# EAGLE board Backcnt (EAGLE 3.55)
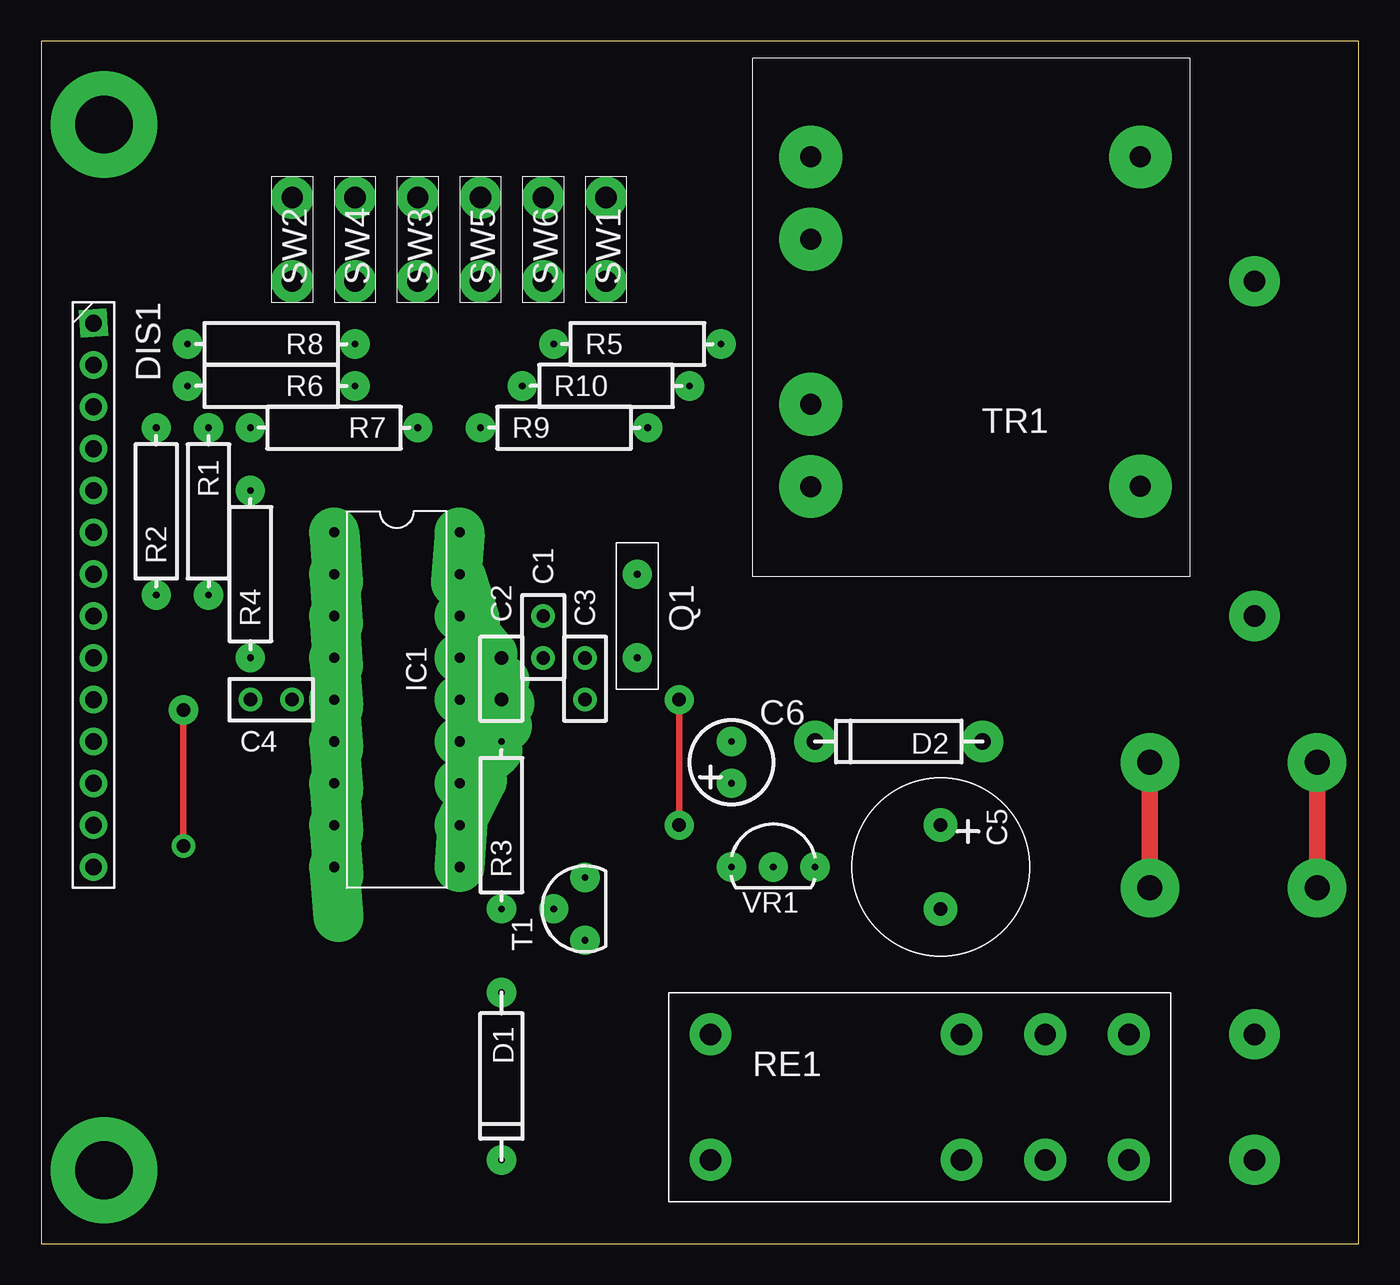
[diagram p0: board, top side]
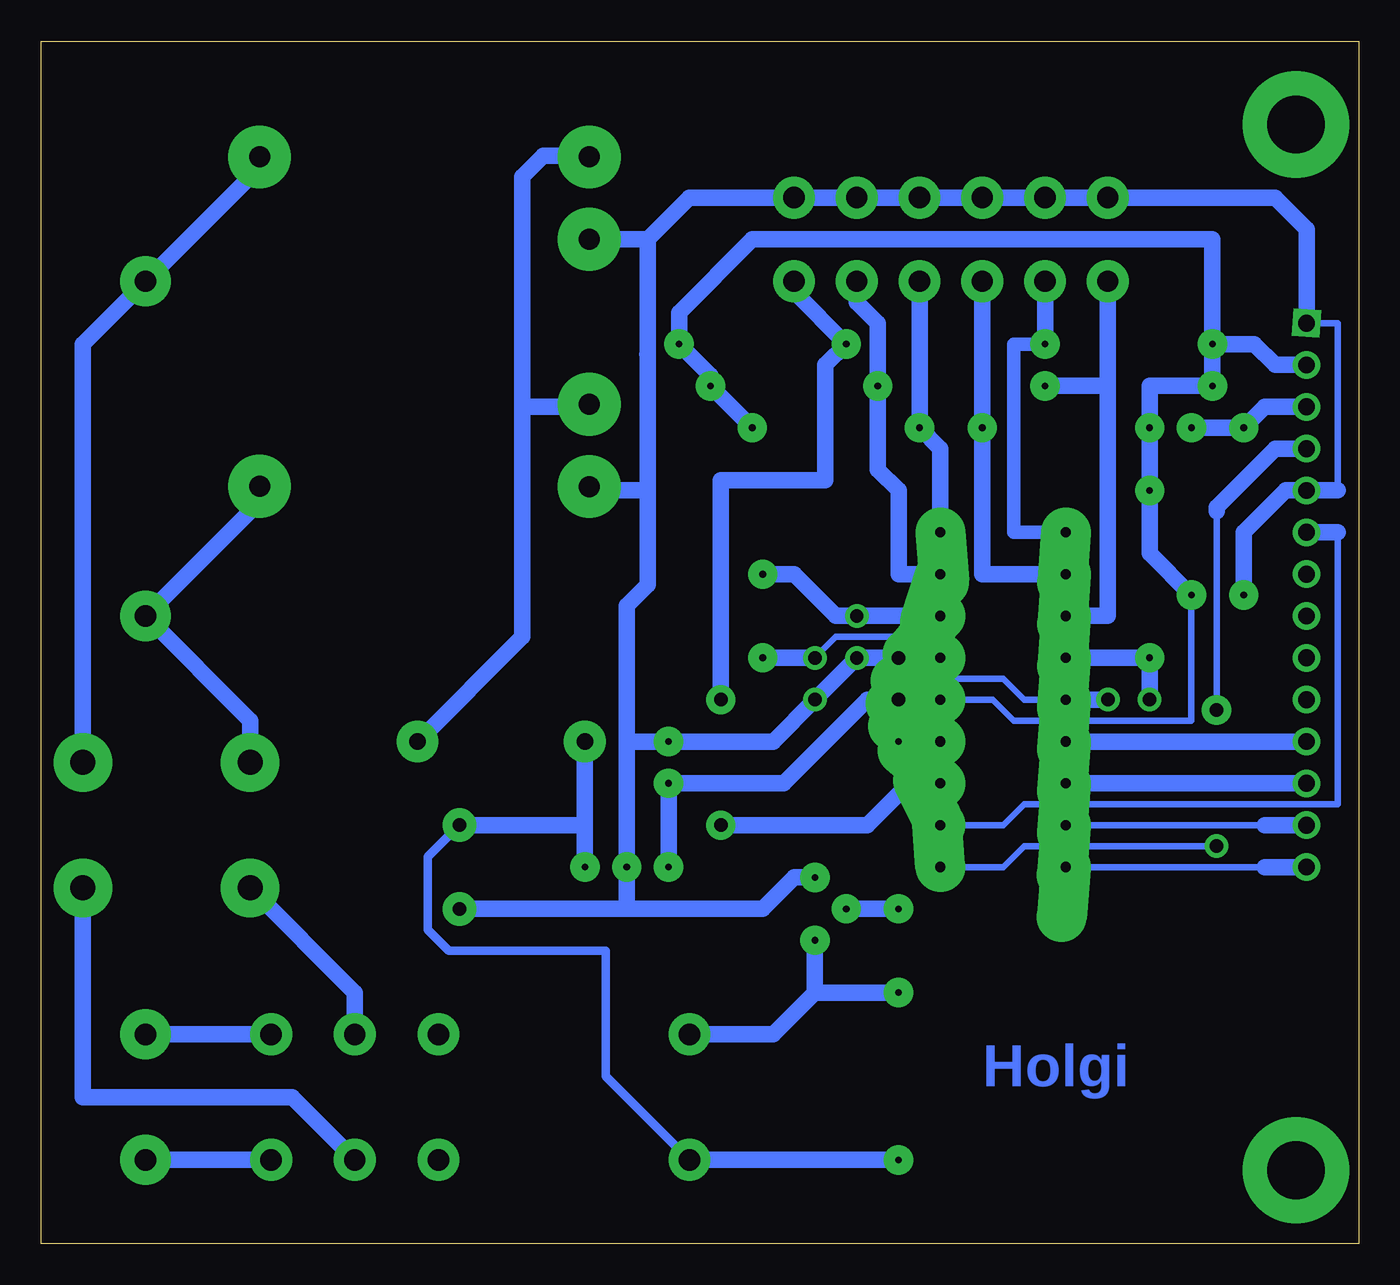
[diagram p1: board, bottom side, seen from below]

Size 80 x 73 mm. Coordinates in mm from the lower left corner, seen from the top.
Outline: 0,0 80,0 80,73 0,73 0,0
Copper layers used: Top, Bottom

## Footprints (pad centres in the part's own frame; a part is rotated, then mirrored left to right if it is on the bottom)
RM2,5 = drill 0.813 pad 1.422 round:  0,0;  2.54,0
KO02 = drill 0.813 pad 2.032 round:  0,0;  5.08,0
KO01 = drill 0.406 pad 1.778 round:  0,0;  2.54,0
O04 = drill 0.406 pad 1.778 round:  0,0;  10.16,0
O_1A = drill 1.016 pad 2.54 round:  0,0;  10.16,0
14_S = drill 1.016 pad 1.676 square:  0,0 | drill 1.016 pad 1.676 round:  5.08,0;  10.16,0;  15.24,0;  20.32,0;  25.4,0;  30.48,0;  33.02,0;  27.94,0;  22.86,0;  17.78,0;  12.7,0;  7.62,0;  2.54,0
L-18B = drill 0.61 pad 3.048 offset:  0,0;  2.54,0;  15.24,0;  17.78,0;  5.08,0;  7.62,0;  12.7,0;  10.16,0;  20.32,0;  20.32,7.62;  17.78,7.62;  15.24,7.62;  12.7,7.62;  10.16,7.62;  7.62,7.62;  5.08,7.62;  2.54,7.62;  0,7.62
ARZ_ST = drill 0.406 pad 1.778 round:  0,0;  5.08,0
S04 = drill 0.406 pad 1.778 round:  0,0;  10.16,0
L2XUM = drill 1.295 pad 2.54 round:  0,0;  15.24,0;  20.32,0;  25.4,0;  25.4,7.62;  20.32,7.62;  15.24,7.62;  0,7.62
H-1POL = drill 1.295 pad 2.54 round:  0,0;  5.08,0
GEL = drill 1.295 pad 3.048 round:  0,0
92 = drill 0.406 pad 1.778 round:  -0.635,0;  1.27,1.905;  3.175,0
-1_5VA = drill 1.27 pad 3.81 round:  -0.508,0;  -0.508,19.99;  19.507,0;  19.507,5.004;  19.507,20.015;  19.507,15.011
HRUNG = drill 3.505 pad 6.452 round:  0,0
92-B = drill 0.406 pad 1.778 round:  -2.54,0;  2.54,0;  0,0

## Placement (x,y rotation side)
C1  33p  [RM2,5]  30.48,35.56 90 top
C2  100n  [RM2,5]  27.94,35.56 270 top
C3  33p  [RM2,5]  33.02,33.02 90 top
C4  100n  [RM2,5]  12.7,33.02 0 top
C5  220u/25V  [KO02]  54.61,25.4 270 top
C6  47u  [KO01]  41.91,27.94 90 top
D1  1N4148  [O04]  27.94,15.24 270 top
D2  1N4001  [O_1A]  57.15,30.48 180 top
DIS1  LCD  [14_S]  3.17,55.88 270 top
IC1  16F84P  [L-18B]  17.78,43.18 270 top
Q1  3,2768MHz  [ARZ_ST]  36.2,40.64 270 top
R1  12k  [S04]  10.16,49.53 270 top
R2  1k  [S04]  6.99,39.37 90 top
R3  2k2  [S04]  27.94,20.32 90 top
R4  10k  [S04]  12.7,35.56 90 top
R5  10k  [S04]  31.11,54.61 0 top
R6  10k  [S04]  19.05,52.07 180 top
R7  10k  [S04]  22.86,49.53 180 top
R8  10k  [S04]  19.05,54.61 180 top
R9  10k  [S04]  26.67,49.53 0 top
R10  10k  [S04]  29.21,52.07 0 top
RE1  12V  [L2XUM]  40.64,5.08 0 top
SW1  Stop/on/off  [H-1POL]  34.29,63.5 270 top
SW1K  SW1K  [GEL]  73.66,38.1 0 top
SW1O  SW1O  [GEL]  73.66,12.7 0 top
SW2  Store  [H-1POL]  15.24,63.5 270 top
SW2K  SW2K  [GEL]  73.66,58.42 0 top
SW2O  SW2O  [GEL]  73.66,5.08 0 top
SW3  Start  [H-1POL]  22.86,63.5 270 top
SW4  Cursor Right  [H-1POL]  19.05,63.5 270 top
SW5  Up  [H-1POL]  26.67,63.5 270 top
SW6  Down  [H-1POL]  30.48,63.5 270 top
T1  BC547  [92]  33.02,19.05 90 top
TR1  MINITRAFO  [-1_5VA]  66.23,65.97 180 top
U$26  BOHRUNG  [HRUNG]  3.81,4.45 0 top
U$27  BOHRUNG  [HRUNG]  3.81,67.94 0 top
VR1  78L05  [92-B]  44.45,22.86 0 top

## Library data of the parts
C1-C5 SW1K SW1O SW2K SW2O U$26 U$27 = holgnorm
C6 D1 D2 IC1 Q1 R1-R10 T1 VR1 = holg_plt
DIS1 = 8031bord
RE1 = bts
SW1-SW6 = taster
TR1 = powamps

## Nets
+5V: C2. C6. DIS1. IC1. R1. R4. R5. R6. R7. R8. R9. R10. VR1.
+12V: C5. D1. D2. RE1. VR1.
GND: C1. C2. C3. C4. C5. C6. DIS1. IC1. R2. SW1. SW2. SW3. SW4. SW5. SW6. T1. TR1. VR1.
N$1: C1. IC1. Q1.
N$2: IC1. R3.
N$3: C3. IC1. Q1.
N$5: C4. IC1. R4.
N$6: IC1. R5. SW1.
N$7: D1. RE1. T1.
N$8: RE1. SW1O.
N$9: IC1. R6. SW2.
N$10: IC1. R7. SW3.
N$11: DIS1. IC1.
N$12: DIS1. IC1.
N$13: DIS1. IC1.
N$14: DIS1. IC1.
N$15: IC1. R8. SW4.
N$16: IC1. R9. SW5.
N$17: IC1. R10. SW6.
N$18: RE1. SW1K. TR1.
N$19: RE1. SW2O.
N$20: RE1. SW2K. TR1.
N$21: D2. TR1.
N$22: DIS1. R1. R2.
N$23: DIS1. IC1.
N$24: DIS1. IC1.
N$25: R3. T1.

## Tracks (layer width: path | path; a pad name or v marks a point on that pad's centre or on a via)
+5V
  Bottom 0.406: 25.4,33.02 22.23,33.02 20.95,31.75 10.16,31.75 R1.
  Bottom 1.016: 25.4,33.02 C2. 29.84,33.02 34.92,27.94 41.91,27.94 41.91,22.86 | R8. 8.89,60.96 36.83,60.96 41.27,56.52 R5. 39.37,52.7 R10. R9. | DIS1. 5.08,53.34 6.35,54.61 R8. | R8. R6. 12.7,52.07 R7. R4. 12.7,41.91 R1.
+12V
  Bottom 0.508: 40.64,5.08 45.72,10.16 45.72,17.78 55.24,17.78 56.52,19.05 56.52,23.5 54.61,25.4
  Bottom 1.016: 46.99,25.4 46.99,22.86 | 54.61,25.4 46.99,25.4 | 46.99,25.4 D2. | D1. 40.64,5.08
GND
  Bottom 0.406: 1.27,45.72 1.27,55.88 3.17,55.88 | 17.78,33.02 20.32,33.02 21.59,34.29 27.94,34.29 27.94,35.56
  Bottom 1.016: 3.17,55.88 3.17,61.59 5.08,63.5 15.24,63.5 19.05,63.5 22.86,63.5 26.67,63.5 30.48,63.5 34.29,63.5 40.64,63.5 43.18,60.96 | 27.94,35.56 30.48,35.56 33.02,33.02 35.56,30.48 C6. 44.45,30.48 | 44.45,30.48 VR1. 44.45,20.32 | 44.45,20.32 C5. | 44.45,20.32 36.2,20.32 34.29,22.23 T1. | 17.78,33.02 C4. | 1.27,45.72 3.17,45.72 4.45,45.72 6.99,43.18 6.99,39.37 | 43.18,60.96 43.18,53.98 | 43.18,53.98 43.18,45.72 | 43.18,45.72 43.18,40.01 44.45,38.73 44.45,30.48 | 43.18,53.98 43.19,53.99 | 46.72,45.96 45.96,45.96 45.72,45.72 43.18,45.72 | 46.72,60.97 45.73,60.97 45.72,60.96 43.18,60.96
N$1
  Bottom 1.016: 25.4,38.1 C1. 31.75,38.1 34.29,40.64 36.2,40.64
N$2
  Bottom 1.016: 25.4,30.48 R3.
N$3
  Bottom 0.406: 25.4,35.56 26.67,36.83 31.75,36.83 C3.
  Bottom 1.016: C3. Q1.
N$5
  Bottom 1.016: 17.78,35.56 12.7,35.56 12.7,33.02
N$6  (via drill 0.81 pad 1.78)
  Top 0.406: v38.73,25.4 v38.73,33.02
  Bottom 1.016: SW1. 34.29,57.78 31.11,54.61 32.38,53.34 32.38,46.35 38.73,46.35 v38.73,33.02 | 25.4,27.94 27.3,27.94 29.84,25.4 v38.73,25.4
N$7
  Bottom 1.016: 33.02,15.24 33.02,18.41 | 33.02,15.24 35.56,12.7 RE1. | 27.94,15.24 33.02,15.24
N$8
  Bottom 1.016: 66.04,12.7 SW1O.
N$9
  Bottom 1.016: 15.24,52.07 SW2. | 15.24,52.07 19.05,52.07 | 15.24,52.07 15.24,38.1 17.78,38.1
N$10
  Bottom 1.016: SW3. 22.86,49.53 22.86,40.64 17.78,40.64
N$11
  Bottom 1.016: 3.17,30.48 17.78,30.48
N$12
  Bottom 1.016: 3.17,27.94 17.78,27.94
N$13
  Bottom 0.406: 5.71,25.4 17.78,25.4
  Bottom 1.016: 3.17,25.4 5.71,25.4
N$14
  Bottom 0.406: 5.71,22.86 17.78,22.86
  Bottom 1.016: 3.17,22.86 5.71,22.86
N$15
  Bottom 0.813: 19.05,54.61 20.95,54.61 20.95,43.18 17.78,43.18
  Bottom 1.016: 19.05,54.61 SW4.
N$16
  Bottom 1.016: SW5. 26.67,49.53 25.4,48.26 IC1.
N$17
  Bottom 1.016: SW6. 30.48,57.15 29.21,55.88 29.21,52.07 29.21,46.99 27.94,45.72 27.94,40.64 25.4,40.64
N$18  (via drill 1.52 pad 3.56)
  Top 1.016: v67.31,21.59 v67.31,29.21
  Bottom 1.016: 60.96,12.7 60.96,15.24 v67.31,21.59 | 66.74,45.98 66.74,45.02 SW1K. 67.31,31.75 v67.31,29.21
N$19
  Bottom 1.016: 66.04,5.08 SW2O.
N$20  (via drill 1.52 pad 3.56)
  Top 1.016: v77.47,21.59 v77.47,29.21
  Bottom 1.016: v77.47,29.21 77.47,54.61 SW2K. 66.74,65.34 66.74,65.97 | 60.96,5.08 64.77,8.89 77.47,8.89 v77.47,21.59
N$21
  Bottom 1.016: 50.8,50.8 50.8,36.83 57.15,30.48 | TR1. 47.46,50.96 47.62,50.8 50.8,50.8 | 46.72,65.97 47.56,65.97 47.62,66.04 49.53,66.04 50.8,64.77 50.8,50.8
N$22
  Bottom 1.016: 3.17,50.8 5.71,50.8 R2. 10.16,49.53
N$23  (via drill 0.81 pad 1.42, 0.81 pad 1.78)
  Top 0.406: v8.64,24.13 v8.64,32.38
  Bottom 0.406: 25.4,22.86 21.59,22.86 20.32,24.13 v8.64,24.13 | v8.64,32.38 8.64,44.45
  Bottom 1.016: 8.64,44.45 8.64,44.7 5.08,48.26 3.17,48.26
N$24
  Bottom 0.406: 1.27,43.18 1.27,26.67 20.32,26.67 21.59,25.4 25.4,25.4
  Bottom 1.016: 1.27,43.18 3.17,43.18
N$25
  Bottom 1.016: 27.94,20.32 31.11,20.32

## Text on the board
Bottom: Holgi
Document: Store | Cursor | Start | Up | Down | Stop | on/off | 1 | 230V | 14 | Last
